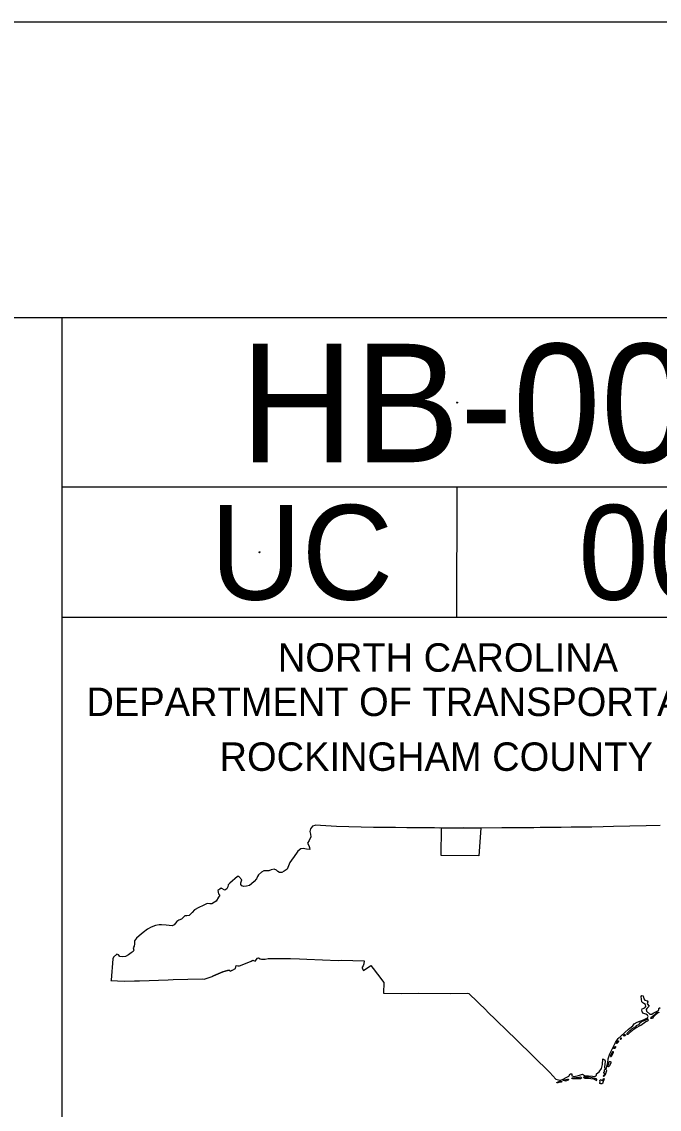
# Model space of a CAD drawing. Extents: x -0.32 to 3.05, y 0 to 1.83.
# Drawn here: x 2.5956 to 2.7302, y 1.6039 to 1.8333 of the extents above; entities that cross this region are included whole.
import ezdxf

# ---------------------------------------------------------------- set-up
doc = ezdxf.new("R2010")
doc.units = 0
for name, color, linetype in [('P_RDY_Limits_of_Construction', 7, 'Continuous'), ('P_RDY_TL_Draft_DNC_Null_Point', 7, 'Continuous'), ('P_RDY_TL_Grass_Shoulder_Normal', 7, 'Continuous')]:
    doc.layers.add(name, color=color, linetype=linetype)

msp = doc.modelspace()

# ---------------------------------------------------------------- linework, layer by layer
at = {"layer": 'P_RDY_Limits_of_Construction'}
msp.add_circle((2.64583, 1.72138), 0.0001, dxfattribs=at)
at = {"layer": 'P_RDY_TL_Draft_DNC_Null_Point'}
msp.add_line((0, 1.83333), (2.83333, 1.83333), dxfattribs=at)
for centre in [(2.6875, 1.75298), (2.64583, 1.72138), (2.72916, 1.72138)]:
    msp.add_circle(centre, 0.0001, dxfattribs=at)
at = {"layer": 'P_RDY_TL_Grass_Shoulder_Normal'}
for p, q in [((2.77083, 1.77083), (0.0625, 1.77083)), ((2.60412, 0.0625), (2.60416, 1.77083)), ((2.77083, 1.73513), (2.60416, 1.73513)), ((2.68749, 1.70763), (2.6875, 1.73513)), ((2.77083, 1.70763), (2.60416, 1.70763))]:
    msp.add_line(p, q, dxfattribs=at)
for points in [[(2.73038, 1.6637), (2.72744, 1.66369), (2.72052, 1.66354), (2.71837, 1.66347), (2.71597, 1.66341), (2.71158, 1.66337), (2.70951, 1.66334), (2.70506, 1.66333), (2.70374, 1.66325), (2.6984, 1.66322), (2.69693, 1.66327), (2.69252, 1.66317), (2.68888, 1.66322), (2.68376, 1.66316), (2.68272, 1.66323), (2.67693, 1.66324), (2.67453, 1.66329), (2.67068, 1.66332), (2.66984, 1.6633), (2.66203, 1.66352), (2.65753, 1.66382), (2.65747, 1.66376), (2.65698, 1.66357), (2.65658, 1.66301), (2.65643, 1.66245), (2.65657, 1.66191), (2.65666, 1.66137), (2.65628, 1.66059), (2.65596, 1.65999), (2.6562, 1.65948), (2.65633, 1.65912), (2.65644, 1.65867), (2.65574, 1.65872), (2.65505, 1.6589), (2.6545, 1.65879), (2.65393, 1.65834), (2.65298, 1.65697), (2.6529, 1.65689), (2.65222, 1.65593), (2.65168, 1.65449), (2.65105, 1.65411), (2.65055, 1.65379), (2.65, 1.65384), (2.64967, 1.65399), (2.64943, 1.65432), (2.64892, 1.6545), (2.64829, 1.6544), (2.64779, 1.65418), (2.64737, 1.65414), (2.64675, 1.65413), (2.64623, 1.65388), (2.64562, 1.65331), (2.64537, 1.65296), (2.64519, 1.65248), (2.64468, 1.6519), (2.64411, 1.65145), (2.64367, 1.65107), (2.64305, 1.6509), (2.64251, 1.65085), (2.64207, 1.65099), (2.64185, 1.65125), (2.64185, 1.65164), (2.64205, 1.65229), (2.64142, 1.65296), (2.64119, 1.65299), (2.63956, 1.65159), (2.63919, 1.65121), (2.63913, 1.65076), (2.6389, 1.65038), (2.6385, 1.65011), (2.63774, 1.65049), (2.63746, 1.65027), (2.63705, 1.64998), (2.63716, 1.64931), (2.63742, 1.64901), (2.63716, 1.64858), (2.63664, 1.64776), (2.63632, 1.64753)], [(2.63632, 1.64753), (2.63575, 1.64718), (2.63535, 1.64719), (2.63479, 1.64725), (2.63391, 1.64688), (2.63303, 1.64643), (2.63207, 1.64591), (2.63157, 1.6454), (2.63126, 1.64503), (2.63097, 1.64475), (2.63046, 1.64469), (2.63004, 1.64465), (2.6297, 1.6443), (2.62933, 1.64394), (2.62879, 1.64375), (2.62838, 1.64346), (2.62782, 1.64275), (2.62741, 1.64257), (2.62614, 1.64267), (2.62514, 1.64278), (2.62461, 1.64279), (2.62383, 1.6426), (2.62297, 1.64227), (2.62217, 1.64188), (2.62124, 1.64117), (2.62041, 1.64045), (2.61983, 1.63994), (2.6194, 1.63938), (2.61942, 1.63877), (2.61937, 1.6383), (2.61917, 1.6379), (2.6193, 1.63743), (2.61917, 1.63711), (2.61873, 1.63686), (2.61814, 1.63643), (2.61753, 1.63611), (2.61684, 1.636), (2.61632, 1.6361), (2.61608, 1.63642), (2.61568, 1.63655), (2.61498, 1.63597), (2.61485, 1.63558), (2.61454, 1.63112), (2.61443, 1.631), (2.61726, 1.63088), (2.61941, 1.63092), (2.62052, 1.63094), (2.62651, 1.63116), (2.62761, 1.63121), (2.63376, 1.63139), (2.63414, 1.6313), (2.63585, 1.63189), (2.63609, 1.63202), (2.63806, 1.63284), (2.63906, 1.63315), (2.63941, 1.6332), (2.63965, 1.63299), (2.63997, 1.63311), (2.64073, 1.63358), (2.64081, 1.63388), (2.64087, 1.63417), (2.64121, 1.63413), (2.64162, 1.6341), (2.64249, 1.63447), (2.64403, 1.63509), (2.6444, 1.63532), (2.6449, 1.63512), (2.64539, 1.63574), (2.6456, 1.6358), (2.64596, 1.63557), (2.64623, 1.63554), (2.64703, 1.63549), (2.64765, 1.6357), (2.64852, 1.63569), (2.65233, 1.63565), (2.65422, 1.63557), (2.6558, 1.63554), (2.66244, 1.63525), (2.66311, 1.6353), (2.66792, 1.63516), (2.66781, 1.63456), (2.66768, 1.63413), (2.66746, 1.63385), (2.66747, 1.6336), (2.66775, 1.63315), (2.66934, 1.63419), (2.6698, 1.63354), (2.67068, 1.63238), (2.67204, 1.63057), (2.67197, 1.62833), (2.67588, 1.62827), (2.6794, 1.62832), (2.68611, 1.6283), (2.6897, 1.62832), (2.68997, 1.6283), (2.69374, 1.62468), (2.69376, 1.62454), (2.70004, 1.6185), (2.70705, 1.61164), (2.70832, 1.61018)], [(2.63997, 1.63311), (2.63965, 1.63299), (2.63941, 1.6332), (2.63906, 1.63315), (2.63806, 1.63284), (2.63609, 1.63202), (2.63585, 1.63189)], [(2.70832, 1.61018), (2.70919, 1.60999), (2.70978, 1.61016), (2.7105, 1.61053), (2.71106, 1.61087), (2.7114, 1.6113), (2.7117, 1.6113), (2.71176, 1.61088), (2.7122, 1.61079), (2.71316, 1.61101), (2.71397, 1.61123), (2.71442, 1.61097), (2.71527, 1.6109), (2.71606, 1.61087), (2.7166, 1.61076), (2.7169, 1.61102), (2.71696, 1.61135), (2.7175, 1.61175), (2.71799, 1.61245), (2.71818, 1.61329), (2.71829, 1.61446), (2.71836, 1.61445), (2.71864, 1.61438), (2.71874, 1.61402), (2.71862, 1.61272), (2.71869, 1.61255), (2.71884, 1.61244), (2.71899, 1.61245), (2.71906, 1.61254), (2.71914, 1.61295), (2.71936, 1.61367), (2.71941, 1.61447), (2.71975, 1.61553), (2.72032, 1.61665), (2.72096, 1.61797), (2.72136, 1.61858), (2.72151, 1.61875), (2.72216, 1.61936), (2.72369, 1.62076), (2.72463, 1.62145), (2.72491, 1.62185), (2.72551, 1.62224), (2.72688, 1.62274), (2.72773, 1.62318), (2.72781, 1.62346), (2.72769, 1.62371), (2.72738, 1.6239), (2.72672, 1.62413), (2.72655, 1.62445), (2.72652, 1.62479), (2.72659, 1.62507), (2.72716, 1.62529), (2.72732, 1.62555), (2.72725, 1.62595), (2.72693, 1.62619), (2.72673, 1.62634), (2.72652, 1.62655), (2.72633, 1.62767), (2.7265, 1.62787), (2.72677, 1.62782), (2.72692, 1.62716), (2.72715, 1.62689), (2.72765, 1.62672), (2.72777, 1.62651), (2.7276, 1.62611), (2.72804, 1.62561), (2.72758, 1.62508), (2.7274, 1.62489), (2.72752, 1.62455), (2.72819, 1.62395), (2.7286, 1.62393), (2.72891, 1.62412), (2.72957, 1.6245), (2.73006, 1.62475), (2.73012, 1.62512), (2.73039, 1.62535)], [(2.724, 1.62048), (2.72347, 1.61997), (2.72334, 1.61983), (2.72331, 1.6197), (2.72337, 1.61962), (2.72362, 1.61968), (2.72413, 1.62016), (2.72457, 1.62058), (2.72526, 1.62101), (2.72631, 1.62162), (2.72738, 1.62235), (2.72776, 1.6225), (2.72785, 1.6226), (2.72794, 1.62279), (2.72774, 1.62287), (2.72746, 1.62272), (2.72677, 1.62243), (2.72645, 1.62229), (2.72602, 1.62195), (2.72579, 1.6217), (2.72531, 1.62147), (2.72517, 1.62126), (2.72469, 1.62093), (2.7245, 1.62091), (2.72438, 1.62079), (2.72434, 1.62073), (2.72403, 1.62049)], [(2.72931, 1.62389), (2.7295, 1.62412), (2.7297, 1.62427), (2.72985, 1.62433), (2.72998, 1.62433), (2.73006, 1.62431), (2.73006, 1.62426), (2.72984, 1.62412), (2.72968, 1.62402), (2.72941, 1.62379), (2.72918, 1.62354), (2.7289, 1.62326), (2.72872, 1.62309), (2.72859, 1.62302), (2.72848, 1.623), (2.72841, 1.62304), (2.7284, 1.62314), (2.72848, 1.62326), (2.72865, 1.6234), (2.72923, 1.62382), (2.72931, 1.6239)], [(2.72115, 1.61786), (2.72128, 1.61807), (2.72141, 1.61821), (2.72149, 1.61827), (2.72155, 1.61827), (2.7216, 1.61823), (2.72163, 1.61817), (2.72156, 1.61809), (2.72145, 1.61794), (2.72135, 1.61784), (2.7212, 1.61776), (2.72116, 1.61776), (2.72113, 1.61778), (2.72112, 1.61781), (2.72115, 1.61786)], [(2.72205, 1.61886), (2.72196, 1.61876), (2.72195, 1.6187), (2.72198, 1.61866), (2.72203, 1.61865), (2.7221, 1.61867), (2.7222, 1.61874), (2.72223, 1.61878), (2.72222, 1.61882), (2.72214, 1.61889), (2.72211, 1.6189), (2.72208, 1.61889), (2.72206, 1.61886)], [(2.72263, 1.61952), (2.72283, 1.61965), (2.7229, 1.61966), (2.72294, 1.61963), (2.72298, 1.61958), (2.72299, 1.61952), (2.72297, 1.61944), (2.72291, 1.61937), (2.72285, 1.61933), (2.7228, 1.61931), (2.72274, 1.6193), (2.72268, 1.61936), (2.72262, 1.61944), (2.72261, 1.61949), (2.72263, 1.61952)], [(2.71989, 1.61512), (2.71987, 1.61497), (2.7199, 1.61496), (2.71996, 1.61497), (2.72004, 1.61502), (2.72009, 1.61508), (2.72052, 1.6158), (2.72053, 1.6159), (2.72052, 1.61595), (2.72045, 1.61599), (2.72039, 1.61599), (2.7203, 1.61594), (2.72025, 1.61587), (2.71992, 1.61522), (2.71989, 1.61512)], [(2.72055, 1.6167), (2.72062, 1.61685), (2.7207, 1.61697), (2.72078, 1.61704), (2.72088, 1.61709), (2.72094, 1.61708), (2.72096, 1.61703), (2.72092, 1.61691), (2.72086, 1.61677), (2.72079, 1.6167), (2.7207, 1.61664), (2.72058, 1.61665), (2.72055, 1.61667), (2.72054, 1.61671)], [(2.71954, 1.61347), (2.71955, 1.61367), (2.71956, 1.61382), (2.71963, 1.6139), (2.71973, 1.61394), (2.71983, 1.61391), (2.71993, 1.61384), (2.71993, 1.61365), (2.71967, 1.61304), (2.71953, 1.61287), (2.7194, 1.6128), (2.71932, 1.61284), (2.71931, 1.61294), (2.71941, 1.61316), (2.71954, 1.61348)], [(2.71865, 1.61191), (2.71856, 1.61177), (2.71843, 1.61168), (2.7184, 1.61164), (2.71841, 1.61158), (2.71856, 1.61143), (2.71864, 1.61136), (2.71867, 1.61134), (2.71867, 1.61125), (2.71837, 1.61094), (2.71835, 1.6109), (2.71844, 1.61083), (2.7185, 1.61085), (2.71863, 1.61093), (2.71886, 1.6112), (2.71911, 1.61204)], [(2.71911, 1.61204), (2.71898, 1.61216), (2.71869, 1.61221), (2.7186, 1.61215), (2.71853, 1.61209), (2.71855, 1.61203), (2.71865, 1.61191)], [(2.70855, 1.60949), (2.7087, 1.60958), (2.70899, 1.6097), (2.70919, 1.60976), (2.70932, 1.60977), (2.70943, 1.60975), (2.70956, 1.60972), (2.70961, 1.60969), (2.70963, 1.60966), (2.70962, 1.60964), (2.70948, 1.60956), (2.70944, 1.60957), (2.70941, 1.6096), (2.70928, 1.60957), (2.70901, 1.60952), (2.70878, 1.60946), (2.70865, 1.60942), (2.7086, 1.60942), (2.70857, 1.60945), (2.70855, 1.60949)], [(2.71012, 1.61008), (2.71084, 1.61018), (2.71098, 1.61017), (2.71105, 1.61015), (2.71102, 1.61004), (2.71092, 1.60996), (2.71062, 1.60984), (2.71038, 1.60981), (2.71001, 1.6099), (2.70991, 1.60995), (2.70998, 1.61003), (2.71014, 1.6101)], [(2.71187, 1.61048), (2.71257, 1.61053), (2.71334, 1.61066), (2.71354, 1.61068), (2.7137, 1.61059), (2.71379, 1.61048), (2.71377, 1.61041), (2.71358, 1.61028), (2.71344, 1.61024), (2.71269, 1.61028), (2.71215, 1.61029), (2.71193, 1.61029), (2.7118, 1.61033), (2.71176, 1.61037), (2.71176, 1.6104), (2.71176, 1.61043), (2.71186, 1.61047)], [(2.71417, 1.61059), (2.71444, 1.61042), (2.71473, 1.61043), (2.71526, 1.61041), (2.71575, 1.61036), (2.7163, 1.61024), (2.71671, 1.61003), (2.71688, 1.60995), (2.71703, 1.61002), (2.71699, 1.61017), (2.71687, 1.61025), (2.71605, 1.61052), (2.7154, 1.61065), (2.71432, 1.61066), (2.71417, 1.61064), (2.71418, 1.61059)], [(2.71785, 1.61009), (2.71812, 1.6099), (2.71819, 1.60987), (2.71829, 1.60999), (2.71842, 1.61031), (2.71849, 1.61035), (2.71855, 1.61025), (2.7183, 1.60951), (2.71824, 1.60934), (2.71803, 1.60923), (2.71784, 1.60922), (2.71767, 1.60929), (2.71762, 1.60946), (2.71769, 1.60966), (2.71767, 1.60994), (2.71769, 1.61), (2.71783, 1.6101), (2.71787, 1.61009)]]:
    msp.add_lwpolyline(points, dxfattribs=at)
msp.add_lwpolyline([(2.69213, 1.65734), (2.68416, 1.65743), (2.68422, 1.66316), (2.68908, 1.66322), (2.69252, 1.66317)], close=True, dxfattribs=at)

# ---------------------------------------------------------------- texts
at = {"layer": 'P_RDY_Limits_of_Construction'}
for s, height, p in [('HB-0035', 0.025, (2.64167, 1.74038)), ('UC', 0.02, (2.6354, 1.71138)), ('005', 0.02, (2.71308, 1.71138))]:
    msp.add_text(s, height=height, dxfattribs=at).set_placement(p)
at = {"layer": 'P_RDY_TL_Grass_Shoulder_Normal'}
for s, p in [('NORTH CAROLINA', (2.64968, 1.69618)), ('DEPARTMENT OF TRANSPORTATION', (2.60929, 1.68683)), ('ROCKINGHAM COUNTY', (2.63738, 1.67526))]:
    msp.add_text(s, height=0.0060037, rotation=0, dxfattribs=at).set_placement(p)

doc.saveas('drawing.dxf')
